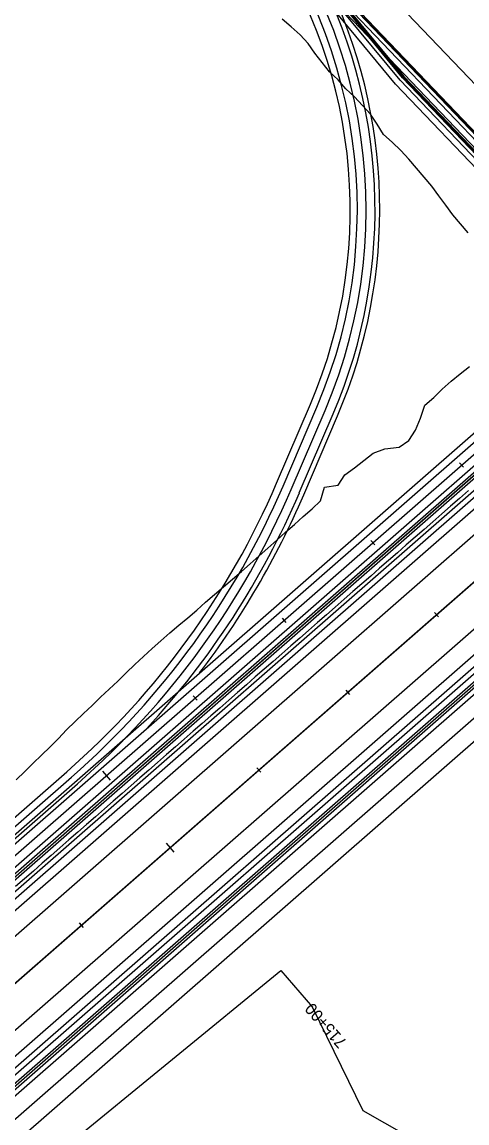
# Model space of a CAD drawing. Extents: x 1300404 to 1323571, y 234004 to 252077.
# Drawn here: x 1310184 to 1310561, y 240349 to 241283 of the extents above; entities that cross this region are included whole.
import ezdxf

# ---------------------------------------------------------------- set-up
doc = ezdxf.new("R2010")
doc.units = 0
for name, color, linetype in [('R_Flooplain', 7, 'Continuous'), ('R_Future', 7, 'Continuous'), ('R_Horz Alg Station Annot', 7, 'Continuous'), ('R_Lane Edge', 7, 'Continuous'), ('R_Shoulder', 7, 'Continuous'), ('R_Sidewalk Edge', 7, 'Continuous'), ('S_CURB_ANNOT', 7, 'Continuous'), ('S_ELECTRIC_UTILITIES_ANNOT', 7, 'Continuous'), ('S_LANDSCAPING_ANNOT', 7, 'Continuous'), ('S_POOL', 7, 'Continuous'), ('S_SANITARY_SEWER_ANNOT', 7, 'Continuous'), ('S_SIGN', 7, 'Continuous'), ('S_TREE_ANNOT', 7, 'Continuous')]:
    doc.layers.add(name, color=color, linetype=linetype)

msp = doc.modelspace()

# ---------------------------------------------------------------- linework, layer by layer
at = {"layer": 'R_Flooplain'}
for p, q in [((1310180.38, 240295.99), (1310403.59, 240478.31)), ((1310403.59, 240478.31), (1310430.47, 240447.32)), ((1310473.27, 240359.27), (1310430.47, 240447.32)), ((1310628.59, 240271.59), (1310473.27, 240359.27))]:
    msp.add_line(p, q, dxfattribs=at)
at = {"layer": 'R_Future'}
for p, q in [((1311714.76, 241726.24), (1309950.43, 240183.5)), ((1311716.07, 241724.73), (1309951.75, 240181.99)), ((1311717.39, 241723.23), (1309953.06, 240180.49)), ((1311720.02, 241720.22), (1309955.69, 240177.48)), ((1310412.25, 241352.34), (1310507.86, 241236.24)), ((1310500.78, 241229.89), (1310405.17, 241345.99)), ((1310504.53, 241233.21), (1310408.91, 241349.31)), ((1310506.77, 241235.21), (1310411.16, 241351.31)), ((1310411.52, 241351.65), (1310507.13, 241235.55)), ((1310504.53, 241233.21), (1310647.25, 241083.69)), ((1310506.77, 241235.21), (1310984.1, 240735.13)), ((1310506.77, 241235.21), (1310984.1, 240735.13)), ((1310507.13, 241235.55), (1310981.19, 240738.9)), ((1310507.13, 241235.55), (1310981.19, 240738.9)), ((1310507.86, 241236.24), (1310967.32, 240754.88)), ((1310507.86, 241236.24), (1310967.32, 240754.88)), ((1310500.78, 241229.89), (1310643.48, 241080.39)), ((1310399.86, 240891.49), (1310428.53, 240958.46)), ((1310405.37, 240889.13), (1310434.04, 240956.1)), ((1310412.27, 240886.18), (1310440.94, 240953.15)), ((1310419.16, 240883.23), (1310447.83, 240950.19)), ((1310422.84, 240881.65), (1310451.51, 240948.62)), ((1310616.69, 240735.53), (1309965.57, 240166.18)), ((1310582.45, 240685.67), (1309975.44, 240154.89)), ((1309920.97, 240383.56), (1310222.09, 240646.86)), ((1309924.92, 240379.04), (1310226.04, 240642.34)), ((1310097.85, 240520.29), (1310230.98, 240636.7))]:
    msp.add_line(p, q, dxfattribs=at)
for centre, radius, start, end in [((1310043.42, 241123.33), 432.42, 336.82333, 43.66667), ((1310043.42, 241123.33), 424.92, 336.82333, 43.66667), ((1310043.42, 241123.33), 418.92, 336.82333, 36.25513), ((1310043.42, 241123.33), 439.92, 336.82333, 28.66161), ((1310043.42, 241123.33), 443.92, 336.82333, 26.18643), ((1309773.83, 241159.51), 680.99, 311.16667, 336.82333), ((1309773.83, 241159.51), 686.99, 311.16667, 336.82333), ((1309773.83, 241159.51), 694.49, 311.16667, 336.82333), ((1309773.83, 241159.51), 701.99, 317.28606, 336.82333), ((1309773.83, 241159.51), 705.99, 322.59605, 336.82333)]:
    msp.add_arc(centre, radius, start, end, dxfattribs=at)
at = {"layer": 'R_Lane Edge'}
for p, q in [((1310412.25, 241352.34), (1311200.16, 240526.88)), ((1309579.79, 240062.65), (1310885.34, 241204.23)), ((1309589.67, 240051.36), (1310895.24, 241192.96))]:
    msp.add_line(p, q, dxfattribs=at)
at = {"layer": 'R_Shoulder'}
for p, q in [((1309575.85, 240067.17), (1310881.38, 241208.74)), ((1309592.3, 240048.35), (1310897.87, 241189.95))]:
    msp.add_line(p, q, dxfattribs=at)
at = {"layer": 'R_Sidewalk Edge'}
for p, q in [((1310378.2, 241381.49), (1310655.54, 241090.93)), ((1310385.11, 241367.02), (1310651.77, 241087.64))]:
    msp.add_line(p, q, dxfattribs=at)
at = {"layer": 'S_CURB_ANNOT'}
for p, q in [((1309593.62, 240046.84), (1310899.19, 241188.45)), ((1309594.93, 240045.34), (1310900.51, 241186.94))]:
    msp.add_line(p, q, dxfattribs=at)
at = {"layer": 'S_ELECTRIC_UTILITIES_ANNOT'}
for points in [[(1310562.4, 241103.84), (1310555.79, 241111.35), (1310549.4, 241119.07), (1310543.4, 241127.17), (1310537.44, 241135.31), (1310531.38, 241143.35), (1310524.96, 241151.04), (1310518.56, 241158.76), (1310511.97, 241166.29), (1310505.12, 241173.58), (1310497.93, 241180.54), (1310490.48, 241187.26), (1310485.18, 241196.02), (1310479.41, 241204.33), (1310472.78, 241211.83), (1310465.98, 241219.17), (1310458.63, 241225.97), (1310452.03, 241233.49), (1310444.72, 241240.34), (1310438.43, 241248.16), (1310432.36, 241256.19), (1310426.55, 241264.47), (1310419.75, 241271.8), (1310412.25, 241278.47), (1310404.66, 241285.05)], [(1310179.04, 240640.12), (1310186.38, 240646.92), (1310193.47, 240654), (1310200.6, 240661.04), (1310207.87, 240667.92), (1310214.89, 240675.08), (1310221.79, 240682.38), (1310229.01, 240689.32), (1310236.14, 240696.35), (1310243.48, 240703.15), (1310250.68, 240710.11), (1310258.01, 240716.92), (1310265.35, 240723.72), (1310272.47, 240730.76), (1310279.6, 240737.81), (1310286.93, 240744.61), (1310294.36, 240751.3), (1310301.84, 240757.94), (1310309.36, 240764.53), (1310316.99, 240771), (1310324.66, 240777.43), (1310332.34, 240783.83), (1310339.68, 240790.63), (1310347.16, 240797.26), (1310354.75, 240803.77), (1310362.59, 240810), (1310370.09, 240816.62), (1310377.59, 240823.23), (1310385.07, 240829.87), (1310392.53, 240836.53), (1310399.99, 240843.19), (1310407.43, 240849.87), (1310414.98, 240856.43), (1310422.32, 240863.23), (1310429.92, 240869.73), (1310437.19, 240876.6), (1310440.42, 240888.1), (1310452.07, 240889.97), (1310457.81, 240898.6), (1310465.82, 240904.62), (1310473.74, 240910.77), (1310481.68, 240916.87), (1310491.57, 240920.76), (1310503.68, 240922.1), (1310512.02, 240927.75), (1310517.74, 240936.4), (1310522, 240946.72), (1310525.69, 240957.69), (1310533.3, 240964.18), (1310540.29, 240971.38), (1310547.81, 240977.97), (1310555.56, 240984.3), (1310563.36, 240990.58)], [(1310562.52, 240885.19), (1310554.99, 240878.61), (1310547.46, 240872.03), (1310539.94, 240865.44), (1310532.41, 240858.86), (1310524.88, 240852.28), (1310517.35, 240845.7), (1310509.82, 240839.11), (1310502.3, 240832.53), (1310494.77, 240825.95), (1310487.24, 240819.37), (1310479.71, 240812.78), (1310472.18, 240806.2), (1310464.66, 240799.62), (1310457.13, 240793.04), (1310449.6, 240786.45), (1310442.07, 240779.87), (1310434.54, 240773.29), (1310427.02, 240766.71), (1310419.49, 240760.12), (1310411.96, 240753.54), (1310404.43, 240746.96), (1310396.9, 240740.38), (1310389.38, 240733.79), (1310381.85, 240727.21), (1310374.32, 240720.63), (1310366.79, 240714.05), (1310359.26, 240707.46), (1310351.74, 240700.88), (1310344.21, 240694.3), (1310336.68, 240687.72), (1310329.15, 240681.13), (1310321.62, 240674.55), (1310314.1, 240667.97), (1310306.57, 240661.39), (1310299.04, 240654.8), (1310291.51, 240648.22), (1310283.98, 240641.64), (1310276.46, 240635.06), (1310268.93, 240628.47), (1310261.4, 240621.89), (1310253.87, 240615.31), (1310246.34, 240608.73), (1310238.82, 240602.14), (1310231.29, 240595.56), (1310223.76, 240588.98), (1310216.23, 240582.4), (1310208.7, 240575.81), (1310201.18, 240569.23), (1310193.65, 240562.65), (1310186.12, 240556.07), (1310178.59, 240549.48)]]:
    msp.add_lwpolyline(points, dxfattribs=at)
at = {"layer": 'S_LANDSCAPING_ANNOT'}
for p, q in [((1308463.14, 238968.01), (1312793.8, 242754.77)), ((1308427.57, 238936.91), (1312398.96, 242409.52)), ((1309180.37, 239595.16), (1312398.96, 242409.52)), ((1309180.37, 239595.16), (1312398.96, 242409.52)), ((1309180.37, 239595.16), (1312051.46, 242105.66)), ((1310151.78, 241665.77), (1311952.58, 239779.15)), ((1310165.59, 241651.3), (1311952.63, 239779.09)), ((1310165.59, 241651.3), (1311952.63, 239779.09)), ((1310223.05, 241550.56), (1311374.36, 240344.37)), ((1309584.71, 240056.98), (1310889.67, 241198.05))]:
    msp.add_line(p, q, dxfattribs=at)
at = {"layer": 'S_POOL'}
for p, q in [((1308396.96, 238971.92), (1312368.36, 242444.53)), ((1308407.83, 238959.5), (1312379.22, 242432.11)), ((1308447.32, 238914.33), (1312418.71, 242386.94)), ((1308458.18, 238901.91), (1312429.57, 242374.52)), ((1309037.78, 239548.19), (1312137.61, 242258.71)), ((1309184.47, 239689.08), (1312131.36, 242265.86)), ((1309193.69, 239678.54), (1312140.58, 242255.32)), ((1309413.86, 239721.62), (1312065.67, 242040.38)), ((1309410.89, 239725), (1311987.97, 241978.41)), ((1309410.89, 239725), (1311987.97, 241978.41))]:
    msp.add_line(p, q, dxfattribs=at)
at = {"layer": 'S_SANITARY_SEWER_ANNOT'}
for points in [[(1310252.28, 240647.36), (1310258.87, 240639.83)], [(1310306.27, 240586.3), (1310312.86, 240578.77)]]:
    msp.add_lwpolyline(points, dxfattribs=at)
at = {"layer": 'S_SIGN'}
for points in [[(1310555.05, 240908.78), (1310558.34, 240905.01)], [(1310479.77, 240842.95), (1310483.06, 240839.19)], [(1310404.49, 240777.12), (1310407.78, 240773.36)], [(1310533.76, 240781.9), (1310537.05, 240778.13)], [(1310329.21, 240711.3), (1310332.5, 240707.54)], [(1310458.48, 240716.07), (1310461.77, 240712.31)], [(1310383.2, 240650.25), (1310386.49, 240646.48)], [(1310232.64, 240518.6), (1310235.93, 240514.83)]]:
    msp.add_lwpolyline(points, dxfattribs=at)
at = {"layer": 'S_TREE_ANNOT'}
for p, q in [((1310372.48, 241392.56), (1310671.99, 241078.77)), ((1310373.35, 241390.92), (1310671.61, 241078.44))]:
    msp.add_line(p, q, dxfattribs=at)

# ---------------------------------------------------------------- texts
at = {"layer": 'R_Horz Alg Station Annot'}
msp.add_text('715+00', height=10, rotation=131.16667, dxfattribs=at).set_placement((1310460.18, 240417.89))

doc.saveas('drawing.dxf')
